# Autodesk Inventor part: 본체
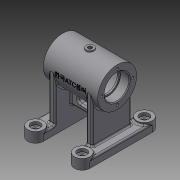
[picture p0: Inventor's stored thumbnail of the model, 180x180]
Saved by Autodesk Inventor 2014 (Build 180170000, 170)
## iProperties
Created: 2015-11
Part Number: 본체
Material: 일반
Document SubType Name: Modeling
Designer: USER
Density: 1 g/cm^3
Appearance: 기본값
Author: USER
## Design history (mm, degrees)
sketch "스케치1"
  geometry: C1 r 25 at (0, 0); 1 further point
  constraints: 1 centre point, 1 coincident
  dimensions: "d0" = 50 diameter of C1
extrude "돌출1" new body sketch "스케치1" stored distance "d1" = 70; taper "d2" = 0 deg
sketch "스케치2"
  geometry: L1 (-28, 25)-(-20, 25); L2 (-20, 25)-(-20, -25); L3 (-20, -25)-(-28, -25); L4 (-28, -25)-(-28, 25); L5 (-35, -25)-(-35, 25) reference; L6 (-35, 25)-(35, 25) reference; L7 (35, 25)-(35, -25) reference; L8 (35, -25)-(-35, -25) reference; L9 (0, 0)-(0, -10); L10 (28, -25)-(28, 25); L11 (28, 25)-(20, 25); L12 (20, 25)-(20, -25); L13 (20, -25)-(28, -25); 1 further point
  constraints: 18 end point, 4 symmetric about line, 2 parallel, 2 perpendicular, 1 horizontal, 1 horizontal alignment, 1 midpoint
  dimensions: "d3" = 20 distance from line of L9.start L2; "d4" = 8 distance between parallel lines of L2 L4; "d5" = 50 distance of L1.end L2.end
extrude "돌출2" join sketch "스케치2" distance "d6" = 68; taper "d7" = 0 deg
sketch "스케치3"
  geometry: L1 (-20, 4)-(20, 4); L2 (20, 4)-(20, -4); L3 (20, -4)-(-20, -4); L4 (-20, -4)-(-20, 4); 3 further points
  constraints: 8 end point, 2 midpoint, 2 parallel, 1 horizontal, 1 horizontal alignment, 1 perpendicular, 1 vertical alignment
  dimensions: "d8" = 8 distance of L1.end L2.end; "d9" = 40 distance of L1.start L1.end
extrude "돌출3" join sketch "스케치3" distance "d10" = 45; taper "d11" = 0 deg
sketch "스케치4"
  geometry: L1 (28, 25)-(20, 25) reference; L2 (-40, 40)-(-20, 40); L3 (-20, 40)-(-20, -40); L4 (-20, -40)-(-40, -40); L5 (-40, -40)-(-40, 40); L6 (0, 0)-(0, 36.88); L7 (28, 25)-(28, -25) reference; L8 (28, -25)-(20, -25) reference; L9 (20, -25)-(20, 25) reference; L10 (20, 25)-(28, 25) reference; L11 (-28, -25)-(-28, 25) reference; L12 (-28, 25)-(-20, 25) reference; L13 (-20, 25)-(-20, -25) reference; L14 (-20, -25)-(-28, -25) reference; L15 (28, -25)-(28, 25); L16 (28, 25)-(20, 25); L17 (40, 40)-(20, 40); L18 (40, -40)-(40, 40); L19 (20, 40)-(20, -40); L20 (20, 25)-(20, -25); L21 (20, -25)-(28, -25); L22 (20, -40)-(40, -40); 8 further points
  constraints: 26 end point, 8 symmetric about line, 5 horizontal alignment, 4 midpoint, 3 parallel, 2 vertical, 1 horizontal, 1 perpendicular, 1 vertical alignment, 8 other
  dimensions: "d12" = 80 distance of L4.end L2.start; "d13" = 20 distance of L2.start L2.end
extrude "돌출4" join sketch "스케치4" distance "d14" = 10; taper "d15" = 0 deg
sketch "스케치5"
  geometry: L1 (28, -25)-(20, -25) reference; L2 (20, -40)-(20, -25) reference; L3 (40, 40)-(40, -40) reference; L4 (20, 25)-(20, 40) reference; L5 (20, -25)-(20, 25) reference; L6 (28, 25)-(28, -25) reference; L7 (20, 25)-(28, 25) reference; L8 (-28, -25)-(-28, 25) reference; L9 (-28, 25)-(-20, 25) reference; L10 (-20, 25)-(-20, -25) reference; L11 (-20, -25)-(-20, -40) reference; L12 (-40, -40)-(-40, 40) reference; L13 (-20, 40)-(-20, 25) reference; L14 (-20, -25)-(-28, -25) reference; C1 r 10 at (-30, 40); C2 r 10 at (30, 40); C3 r 10 at (30, -40); C4 r 10 at (-30, -40); A1 r 10 centre (30, -40) between (20, -40) and (40, -40) reference; A2 r 10 centre (30, 40) between (40, 40) and (20, 40) reference; A3 r 10 centre (-30, -40) between (-40, -40) and (-20, -40) reference; A4 r 10 centre (-30, 40) between (-20, 40) and (-40, 40) reference; 1 further point
  constraints: 4 centre point, 4 coincident, 2 concentric
  dimensions: "d16" = 20 diameter of C3; "d17" = 20 diameter of C2
extrude "돌출5" join sketch "스케치5" distance "d18" = 3; taper "d19" = 0 deg
sketch "스케치6"
  geometry: L1 (0, 0)-(40, 0) reference; L2 (12, -10.322)-(28, -10.322); L3 (12, -13.822)-(28, -13.822); L4 (28, -6.822)-(12, -6.822); L5 (-15, 0)-(-15, 49.356) reference; L6 (-15, 49.356)-(55, 49.356) reference; L7 (55, 49.356)-(55, 0) reference; L8 (55, 0)-(48, 0) reference; L9 (48, 0)-(48, -33.322) reference; L10 (48, -33.322)-(60, -33.322) reference; L11 (60, -33.322)-(60, -43.322) reference; L12 (60, -43.322)-(40, -43.322) reference; L13 (40, -43.322)-(40, -20.322) reference; L14 (40, -20.322)-(0, -20.322) reference; L15 (0, 0)-(0, -20.322) reference; L16 (40, 0)-(0, 0) reference; L17 (40, -20.322)-(40, 0) reference; L18 (-8, 0)-(-15, 0) reference; L19 (-8, -33.322)-(-8, 0) reference; L20 (-20, -33.322)-(-8, -33.322) reference; L21 (-20, -43.322)-(-20, -33.322) reference; L22 (0, -43.322)-(-20, -43.322) reference; L23 (0, -20.322)-(0, -43.322) reference; A1 r 3.5 centre (12, -10.322) between (12, -6.822) and (12, -13.822); A2 r 3.5 centre (28, -10.322) between (28, -13.822) and (28, -6.822); 3 further points
  constraints: 8 end point, 4 point on circle, 4 tangent, 2 centre point, 2 midpoint, 2 parallel, 1 vertical alignment
  dimensions: "d20" = 7 distance between parallel lines of L3 L4; "d21" = 16 distance of L2.end L2.start; "d22" = 33 distance from line of L22 point (20, -10.322)
extrude "돌출6" cut sketch "스케치6" distance "d23" = 8; taper "d24" = 0 deg
sketch "스케치7"
  geometry: C1 r 21 at (0, 0); 1 further point
  constraints: 1 centre point, 1 coincident
  dimensions: "d25" = 42 diameter of C1
extrude "돌출7" cut sketch "스케치7" stored distance "d26" = 42; taper "d27" = 0 deg
sketch "스케치8"
  geometry: C1 r 14 at (0, 0); 1 further point
  constraints: 1 centre point, 1 coincident
  dimensions: "d28" = 28 diameter of C1
extrude "돌출8" cut sketch "스케치8" stored distance "d29" = 46; taper "d30" = 0 deg
sketch "스케치9"
  geometry: L1 (0, 0)-(14, -24.249); L2 (0, -21)-(0, 0); L3 (11.403, -19.751)-(6.207, -22.751); L4 (6.207, -22.751)-(8.804, -27.249); L5 (8.804, -27.249)-(14, -24.249); L6 (14, -24.249)-(11.403, -19.751)
  constraints: 12 end point, 3 perpendicular, 1 point on line, 1 vertical
  dimensions: "d31" = 30 deg angle of L1 L2; "d32" = 28 distance of L1.start L1.end; "d34" = 12 diameter of L4 L1; "d35" = 5.19376 distance of L3.end L4.end
revolve "회전1" sketch "스케치9" stored, may be unused: angle "d36" = 90 deg
node "작업 평면1"
sketch "스케치10"
  geometry: C1 r 5 at (0, 0); 1 further point
  constraints: 1 centre point, 1 coincident
  dimensions: "d37" = 10 diameter of C1
extrude "돌출9" join sketch "스케치10" stored distance "d38" = 3; taper "d39" = 0 deg
sketch "스케치11"
  geometry: C1 r 25 at (0, 0) reference; C2 r 16 at (0, 0)
  constraints: 1 centre point, 1 coincident
  dimensions: "d40" = 32 diameter of C2
extrude "돌출10" cut sketch "스케치11" distance "d41" = 12; taper "d42" = 0 deg
sketch "스케치12"
  geometry: C1 r 16 at (0, 0) reference; 1 further point
  constraints: 1 horizontal alignment
  dimensions: "d43" = 20 distance of C1.centre point (-20, 0)
hole "구멍1" sketch "스케치12" at (-20, 0) diameter "d44" = 3.242; stored, may be unused: countersink angle "d48" = 90 deg, drill point angle "d50" = 118 deg; dims "d45" = 8, "d46" = 4, "d47" = 2, "d49" = 10
sketch "스케치13"
  geometry: L1 (58, -65)-(50, -65) reference; L2 (50, -65)-(50, -15) reference; L3 (50, -15)-(58, -15) reference; L4 (58, -15)-(58, -65) reference; L5 (2, -65)-(2, -15) reference; L6 (2, -15)-(10, -15) reference; L7 (10, -15)-(10, -65) reference; L8 (10, -65)-(2, -65) reference; C1 r 10 at (0, 0) reference; C2 r 10 at (0, -80) reference; C3 r 10 at (60, -80) reference; C4 r 10 at (60, 0) reference; 5 further points
  constraints: 4 coincident
hole "구멍2" sketch "스케치13" at (0, 0), (60, 0), (60, -80), (0, -80) diameter "d54" = 6; stored, may be unused: countersink angle "d58" = 90 deg, drill point angle "d60" = 118 deg; dims "d55" = 8, "d56" = 12, "d57" = 4, "d59" = 10
sketch "스케치14"
  geometry: C1 r 5 at (0, 0) reference; 1 further point
  constraints: 1 coincident
hole "구멍3" sketch "스케치14" at (0, 0) diameter "d61" = 5.188; stored, may be unused: countersink angle "d65" = 90 deg, drill point angle "d67" = 118 deg; dims "d62" = 10, "d63" = 12, "d64" = 4, "d66" = 10
sketch "스케치15"
  geometry: C1 r 6 at (0, 0) reference; 1 further point
  constraints: 1 coincident
hole "구멍4" sketch "스케치15" at (0, 0) diameter "d68" = 5.188; stored, may be unused: countersink angle "d72" = 90 deg, drill point angle "d74" = 118 deg; dims "d69" = 10, "d70" = 12, "d71" = 4, "d73" = 10
fillet "모깎기1" dims "d75" = 0.3
fillet "모깎기2" dims "d76" = 0.3
sketch "스케치16"
  geometry: L1 (0, -58)-(8, -58) reference; L2 (8, -58)-(20, -58) reference; L3 (20, -58)-(20, -68) reference; L4 (20, -68)-(0, -68) reference; L5 (0, -68)-(0, -58) reference; L6 (0, -58)-(0, 0) reference; L7 (0, 0)-(8, 0) reference; L8 (8, 0)-(15, 0) reference; L9 (8, 0)-(8, -58) reference; L10 (-40, 0)-(0, 0) reference; L11 (-40, 0)-(-40, -58) reference; L12 (-40, -58)-(-40, -68) reference; L13 (-40, -68)-(-60, -68) reference; L14 (-60, -68)-(-60, -58) reference; L15 (-60, -58)-(-48, -58) reference; L16 (-48, -58)-(-40, -58) reference; L17 (-48, 0)-(-40, 0) reference; L18 (-48, -58)-(-48, 0) reference; L19 (-55, 0)-(-48, 0) reference; L20 (-55, 25)-(15, 25) reference; 3 further points
  constraints: 1 coincident, 1 midpoint, 1 other
  dimensions: "d79" = 25 distance from line of L20 point (-20, 0)
  node "절단 모서리 투영6"
fillet "모깎기3" dims "d77" = 2
fillet "모깎기4" dims "d78" = 2
feature "엠보싱1" dims "d8" = 8, "d9" = 40, "d80" = 0.5, "d81" = 0
fillet "모깎기5" dims "d82" = 3
fillet "모깎기6" dims "d83" = 2
fillet "모깎기7" dims "d84" = 2
chamfer "모따기1" distance "d85" = 1; stored, may be unused: second distance "d86" = 2, angle "d87" = 45 deg
node "솔리드1"
mirror "대칭1"
pattern_circular "원형 패턴1" dims angle "d52" = 360 deg
mirror "대칭2"
node "절단 모서리 투영1"
node "절단 모서리 투영2"
node "절단 모서리 투영3"
node "절단 모서리 투영4"
node "절단 모서리 투영5"
